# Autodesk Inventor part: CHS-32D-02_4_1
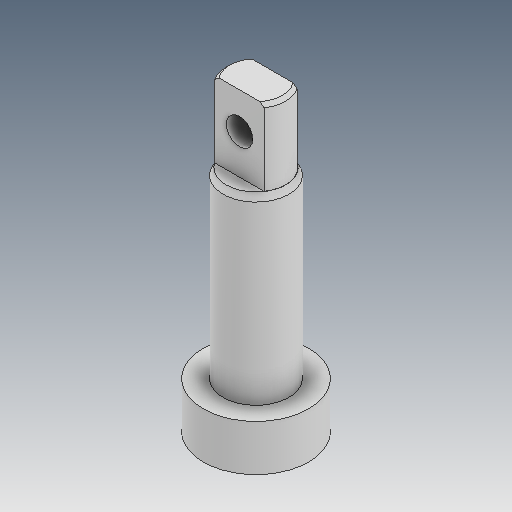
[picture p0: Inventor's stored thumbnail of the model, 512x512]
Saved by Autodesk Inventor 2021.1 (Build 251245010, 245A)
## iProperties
Created: 2021-05
Part Number: CHS-32D-02_4_1
Material: Ogólny
Document SubType Name: Modeling
Designer: user
Density: 1 g/cm^3
Appearance: Domyślna
Author: user
Revision Number: ÈÎºÎ
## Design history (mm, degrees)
feature "NONE"
node "Bryła1"
